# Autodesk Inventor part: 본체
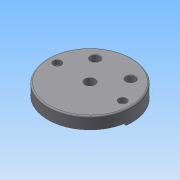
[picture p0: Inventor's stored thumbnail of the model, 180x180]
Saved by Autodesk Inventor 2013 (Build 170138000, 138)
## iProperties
Created: 2015-04
Part Number: 본체
Material: 일반
Document SubType Name: Modeling
Designer: Administrator
Density: 1 g/cm^3
Author: Administrator
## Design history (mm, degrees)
sketch "스케치1"
  geometry: C1 r 95 at (0, 0); 1 further point
  constraints: 1 centre point, 1 coincident
  dimensions: "d0" = 190 diameter of C1
extrude "돌출1" new body sketch "스케치1" distance "d1" = 32; taper "d2" = 0 deg
sketch "스케치28"
  geometry: L1 (89.265, -11.482)-(94.249, -11.918); L2 (-89.157, -12.293)-(-94.143, -12.729); L3 (-114.519, 0)-(114.519, 0); C1 r 95 at (0, 0) reference; A1 r 95 centre (0, 0) between (94.249, -11.918) and (-94.143, -12.729); A2 r 90 centre (0, 0) between (89.265, -11.482) and (-89.157, -12.293); 1 further point
  constraints: 6 end point, 4 point on circle, 3 coincident, 2 centre point, 1 horizontal, 1 midpoint
  dimensions: "d90" = 190 diameter of A1; "d91" = 180 diameter of A2; "d92" = 5 deg angle of L1 L3; "d93" = 5 deg angle of L3 L2; "d94" = 4.98682 horizontal distance of L2.start L2.end; "d95" = 4.98488 horizontal distance of L1.start L1.end
extrude "돌출17" cut sketch "스케치28" distance "d96" = 5; taper "d97" = 0 deg
sketch "스케치29"
  geometry: C1 r 90 at (0, 0); A1 r 90 centre (0, 0) between (-89.157, -12.293) and (89.265, -11.482) reference
  constraints: 1 centre point, 1 coincident
  dimensions: "d98" = 180 diameter of C1
extrude "돌출18" cut sketch "스케치29" distance "d99" = 13; taper "d100" = 0 deg
sketch "스케치30"
  geometry: C1 r 90 at (0, 0) reference; A1 r 9 centre (-50, -19) between (-59, -19) and (-41, -19); A2 r 9 centre (50, -19) between (59, -19) and (41, -19); A3 r 41 centre (0, -19) between (-41, -19) and (41, -19); A4 r 59 centre (0, -19) between (-59, -19) and (59, -19)
  constraints: 8 point on circle, 4 centre point, 2 horizontal alignment, 2 tangent, 1 coincident, 1 vertical alignment
  dimensions: "d101" = 18 diameter of A1; "d102" = 18 diameter of A2; "d103" = 82 diameter of A3; "d104" = 118 diameter of A4; "d105" = 19 distance of A4.centre C1.centre
extrude "돌출19" cut sketch "스케치30" distance "d106" = 5; taper "d107" = 0 deg
sketch "스케치32"
  geometry: L1 (-89.196, 12)-(-40.249, 12); L2 (40.249, 12)-(89.196, 12); C1 r 90 at (0, 0) reference; A1 r 42 centre (0, 0) between (40.249, 12) and (-40.249, 12); A2 r 90 centre (0, 0) between (89.196, 12) and (-89.196, 12)
  constraints: 4 end point, 4 point on circle, 2 centre point, 2 coincident, 2 horizontal
  dimensions: "d110" = 84 diameter of A1; "d113" = 180 diameter of A2; "d114" = 48.94719 distance of L2.start L2.end; "d115" = 48.94719 distance of L1.start L1.end
extrude "돌출20" cut sketch "스케치32" distance "d116" = 12; taper "d117" = 0 deg
sketch "스케치33"
  geometry: C1 r 35 at (0, 0); A1 r 90 centre (0, 0) between (-89.196, 12) and (89.196, 12) reference
  constraints: 1 centre point, 1 coincident
  dimensions: "d118" = 70 diameter of C1
extrude "돌출21" join sketch "스케치33" distance "d119" = 10; taper "d120" = -10 deg
sketch "스케치34"
  geometry: C1 r 33.237 at (0, 0) reference; C2 r 25 at (0, 0)
  constraints: 1 centre point, 1 coincident
  dimensions: "d121" = 50 diameter of C2
extrude "돌출22" cut sketch "스케치34" distance "d122" = 15; taper "d123" = 0 deg
sketch "스케치35"
  geometry: C1 r 25 at (0, 0) reference; C2 r 11.5 at (0, 0)
  constraints: 1 centre point, 1 coincident
  dimensions: "d124" = 23 diameter of C2
extrude "돌출23" cut sketch "스케치35" stored distance "d125" = 15; taper "d126" = 0 deg
sketch "스케치36"
  geometry: C1 r 15 at (40, 52); C2 r 15 at (-40, 52); A1 r 90 centre (0, 0) between (89.196, 12) and (-89.196, 12) reference
  constraints: 2 centre point, 1 horizontal alignment
  dimensions: "d127" = 30 diameter of C1; "d128" = 30 diameter of C2; "d129" = 52 vertical distance of A1.centre C1.centre; "d130" = 80 distance of C1.centre C2.centre; "d131" = 40 horizontal distance of A1.centre C2.centre
extrude "돌출24" join sketch "스케치36" distance "d132" = 25; taper "d133" = 0 deg
sketch "스케치37"
  geometry: C1 r 15 at (0, 0) reference; C2 r 15 at (80, 0) reference; C3 r 10 at (0, 0); C4 r 10 at (80, 0); 1 further point
  constraints: 2 centre point, 2 coincident
  dimensions: "d134" = 20 diameter of C3; "d135" = 20 diameter of C4
extrude "돌출25" cut sketch "스케치37" stored distance "d136" = 25; taper "d137" = 0 deg
sketch "스케치39"
  geometry: C1 r 11.5 at (0, 0) reference; 2 further points
  constraints: 2 horizontal alignment
  dimensions: "d144" = 148 distance of point (74, 0) point (-74, 0); "d146" = 74 distance of point (-74, 0) C1.centre
hole "구멍1" sketch "스케치39" at (-74, 0), (74, 0) diameter "d147" = 11; stored, may be unused: countersink angle "d151" = 90 deg, drill point angle "d153" = 118 deg; dims "d148" = 6, "d149" = 18, "d150" = 11, "d152" = 8
fillet "모깎기1" dims "d154" = 10
sketch "스케치40"
  geometry: L1 (-6, 17.5)-(6, 17.5); L2 (6, 17.5)-(6, -17.5); L3 (6, -17.5)-(-6, -17.5); L4 (-6, -17.5)-(-6, 17.5); C1 r 10 at (0, 0) reference; 3 further points
  constraints: 8 end point, 2 midpoint, 2 parallel, 1 horizontal, 1 horizontal alignment, 1 perpendicular, 1 vertical alignment
  dimensions: "d155" = 12 distance of L1.start L1.end; "d157" = 35 distance of L1.end L2.end
extrude "돌출26" cut sketch "스케치40" distance "d158" = 3; taper "d159" = 0 deg
sketch "스케치41"
  geometry: L1 (-6, 17.5)-(6, 17.5); L2 (6, 17.5)-(6, -17.5); L3 (6, -17.5)-(-6, -17.5); L4 (-6, -17.5)-(-6, 17.5); C1 r 10 at (0, 0) reference; 3 further points
  constraints: 8 end point, 2 midpoint, 2 parallel, 1 horizontal, 1 horizontal alignment, 1 perpendicular, 1 vertical alignment
  dimensions: "d160" = 12 distance of L1.start L1.end; "d162" = 35 distance of L1.end L2.end
extrude "돌출27" cut sketch "스케치41" distance "d163" = 3; taper "d164" = 0 deg
fillet "모깎기2" dims "d165" = 3
fillet "모깎기3" dims "d166" = 0.3
fillet "모깎기4" dims "d167" = 3
chamfer "모따기1" distance "d168" = 1; stored, may be unused: second distance "d169" = 2, angle "d170" = 45 deg
sketch "스케치44"
  geometry: C1 r 5.5 at (-74, 0) reference; C2 r 5.5 at (74, 0) reference; C3 r 9 at (-74, 0); C4 r 9 at (74, 0)
  constraints: 2 centre point, 2 coincident
  dimensions: "d171" = 18 diameter of C3; "d172" = 18 diameter of C4
extrude "돌출28" join sketch "스케치44" distance "d173" = 10; taper "d174" = 0 deg
fillet "모깎기5" dims "d175" = 3
fillet "모깎기6" dims "d176" = 3
fillet "모깎기7" dims "d177" = 3
fillet "모깎기8" dims "d178" = 3
chamfer "모따기2" distance "d179" = 1; stored, may be unused: second distance "d180" = 2, angle "d181" = 45 deg
sketch "스케치16"
  geometry: L1 (89.786, -6.199)-(94.768, -6.635); L2 (-89.413, -10.26)-(-94.396, -10.696); L3 (-110.704, 0)-(110.704, 0); C1 r 95 at (0, 0) reference; A1 r 95 centre (0, 0) between (-94.396, -10.696) and (94.768, -6.635); A2 r 90 centre (0, 0) between (-89.413, -10.26) and (89.786, -6.199); 1 further point
  constraints: 6 end point, 4 point on circle, 3 coincident, 2 centre point, 2 horizontal alignment, 1 horizontal, 1 midpoint
  dimensions: "d39" = 190 diameter of A1; "d40" = 180 diameter of A2; "d43" = 4.98177 horizontal distance of L1.start L1.end; "d44" = 5 deg angle of L1 L3; "d45" = 5 deg angle of L2 L3; "d46" = 4.98269 horizontal distance of L2.start L2.end
sketch "스케치22"
  geometry: L1 (89.689, -7.471)-(94.67, -7.907); L2 (-89.885, -4.553)-(-94.869, -4.989); L3 (-111.534, 0)-(111.534, 0); C1 r 95 at (0, 0) reference; A1 r 95 centre (0, 0) between (94.67, -7.907) and (-94.869, -4.989); A2 r 90 centre (0, 0) between (89.689, -7.471) and (-89.885, -4.553); 1 further point
  constraints: 6 end point, 4 point on circle, 3 coincident, 2 centre point, 1 horizontal, 1 midpoint
  dimensions: "d60" = 190 diameter of A1; "d61" = 180 diameter of A2; "d64" = 5 deg angle of L2 L3; "d65" = 5 deg angle of L1 L3; "d66" = 4.98415 horizontal distance of L2.start L2.end; "d67" = 4.98101 horizontal distance of L1.start L1.end
extrude "돌출11" cut sketch "스케치22" distance "d68" = 5; taper "d69" = 0 deg
sketch "스케치24"
  geometry: C1 r 90 at (0, 0); A1 r 9 centre (46.249, -19) between (54.574, -22.42) and (37.924, -15.58) reference; A2 r 59 centre (0, 0) between (-54.574, -22.42) and (54.574, -22.42) reference; A3 r 9 centre (-46.249, -19) between (-37.924, -15.58) and (-54.574, -22.42) reference; A4 r 41 centre (0, 0) between (-37.924, -15.58) and (37.924, -15.58) reference; A5 r 90 centre (0, 0) between (-89.885, -4.553) and (89.689, -7.471) reference
  constraints: 1 centre point, 1 coincident
  dimensions: "d78" = 180 diameter of C1
extrude "돌출13" cut sketch "스케치24" distance "d79" = 14; taper "d80" = 0 deg
sketch "스케치25"
  geometry: C1 r 95 at (0, 0) reference; C2 r 11.5 at (0, 0)
  constraints: 1 centre point, 1 coincident
  dimensions: "d81" = 23 diameter of C2
extrude "돌출14" cut sketch "스케치25" stored distance "d82" = 14; taper "d83" = 0 deg
sketch "스케치26"
  geometry: C1 r 11.5 at (0, 0) reference; C2 r 90 at (0, 0) reference; C3 r 35 at (0, 0)
  constraints: 1 centre point, 1 coincident
  dimensions: "d84" = 70 diameter of C3
extrude "돌출15" join sketch "스케치26" distance "d85" = 10; taper "d86" = -10 deg
sketch "스케치27"
  geometry: C1 r 33.237 at (0, 0) reference; C2 r 25 at (0, 0)
  constraints: 1 centre point, 1 coincident
  dimensions: "d87" = 50 diameter of C2
extrude "돌출16" cut sketch "스케치27" distance "d88" = 15; taper "d89" = 0 deg
extrude "돌출8" cut sketch "스케치16" distance "d47" = 5; taper "d48" = 0 deg
sketch "스케치17"
  geometry: C1 r 90 at (0, 0); A1 r 90 centre (0, 0) between (-89.413, -10.26) and (89.786, -6.199) reference
  constraints: 1 centre point, 1 coincident
  dimensions: "d49" = 180 diameter of C1
extrude "돌출9" cut sketch "스케치17" distance "d50" = 5; taper "d51" = 0 deg
sketch "스케치18"
  geometry: A1 r 90 centre (0, 0) between (89.786, -6.199) and (-89.413, -10.26) reference; A2 r 9 centre (-46.249, -19) between (-54.574, -22.42) and (-37.924, -15.58); A3 r 9 centre (46.249, -19) between (54.574, -22.42) and (37.924, -15.58); A4 r 41 centre (0, 0) between (-37.924, -15.58) and (37.924, -15.58); A5 r 59 centre (0, 0) between (-54.574, -22.42) and (54.574, -22.42)
  constraints: 8 point on circle, 4 centre point, 2 coincident, 2 tangent, 1 horizontal alignment
  dimensions: "d52" = 18 diameter of A2; "d53" = 18 diameter of A3; "d54" = 82 diameter of A4; "d55" = 118 diameter of A5; "d56" = 19 vertical distance of A2.centre A5.centre
extrude "돌출10" cut sketch "스케치18" distance "d57" = 13; taper "d58" = 0 deg
sketch "스케치2"
  geometry: C1 r 95 at (0, 0) reference; C2 r 90 at (0, 0)
  constraints: 1 centre point, 1 coincident
  dimensions: "d3" = 180 diameter of C2
node "작업 평면1"
sketch "스케치9"
  geometry: C1 r 90 at (0, 0) reference; C2 r 35 at (0, 0)
  constraints: 1 centre point, 1 coincident
  dimensions: "d6" = 70 diameter of C2
extrude "돌출3" join sketch "스케치9" distance "d7" = 10; taper "d8" = -10 deg
node "작업 평면3"
sketch "스케치10"
  geometry: C1 r 33.237 at (0, 0) reference; C2 r 25 at (0, 0)
  constraints: 1 centre point, 1 coincident
  dimensions: "d9" = 50 diameter of C2
extrude "돌출4" cut sketch "스케치10" distance "d10" = 15; taper "d11" = 0 deg
node "작업 평면4"
sketch "스케치11"
  geometry: C1 r 25 at (0, 0) reference; C2 r 11.5 at (0, 0)
  constraints: 1 centre point, 1 coincident
  dimensions: "d12" = 23 diameter of C2
extrude "돌출5" cut sketch "스케치11" stored distance "d13" = 15; taper "d14" = 0 deg
node "작업 평면2"
sketch "스케치13"
  geometry: C1 r 35 at (0, 0) reference; C2 r 90 at (0, 0) reference; C3 r 42 at (0, 0); A1 r 9 centre (-50, -19) between (-59, -19) and (-41, -19); A2 r 9 centre (50, -19) between (59, -19) and (41, -19); A3 r 41 centre (0, -19) between (-41, -19) and (41, -19); A4 r 59 centre (0, -19) between (-59, -19) and (59, -19)
  constraints: 8 point on circle, 5 centre point, 2 coincident, 2 horizontal alignment, 2 tangent, 1 vertical alignment
  dimensions: "d21" = 18 diameter of A1; "d22" = 18 diameter of A2; "d24" = 84 diameter of C3; "d25" = 82 diameter of A3; "d26" = 19 distance of A3.centre C1.centre; "d27" = 118 diameter of A4
sketch "스케치14"
  geometry: L1 (94.907, -4.211)-(89.921, -3.775); L2 (-89.893, -4.387)-(-94.878, -4.823); L3 (-103.888, 0)-(103.888, 0); C1 r 95 at (0, 0) reference; A1 r 95 centre (0, 0) between (94.907, -4.211) and (-94.878, -4.823); A2 r 90 centre (0, 0) between (89.921, -3.775) and (-89.893, -4.387); 1 further point
  constraints: 6 end point, 4 point on circle, 3 coincident, 2 centre point, 1 horizontal, 1 midpoint
  dimensions: "d28" = 190 diameter of A1; "d29" = 180 diameter of A2; "d30" = 5 deg angle of L1 L3; "d31" = 5.00487 distance of L1.start L1.end; "d32" = 5 deg angle of L2 L3; "d34" = 5.00351 distance of L2.start L2.end
extrude "돌출6" cut sketch "스케치14" distance "d35" = 5; taper "d36" = 0 deg
sketch "스케치15"
  geometry: L1 (-89.893, -4.387)-(0, 0); L2 (0, 0)-(89.921, -3.775); A1 r 90 centre (0, 0) between (-89.893, -4.387) and (89.921, -3.775) reference
  constraints: 4 end point
extrude "돌출7" cut sketch "스케치15" distance "d37" = 5; taper "d38" = 0 deg
node "솔리드1"
node "투영된 루프1"
other parameters: "d112" = 12
